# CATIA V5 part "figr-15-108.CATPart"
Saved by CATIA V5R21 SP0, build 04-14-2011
Part number: Part1
Bounding box of the stored display mesh (mm): x -60.955 to 60.955, y -33.748 to 33.748, z 0 to 6.052
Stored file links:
  D:\CATIA V5R21 E-RESOURCES\CATIA-V5R21\catia-v5r21-prt\c15-catia-v5r20-prt\c15-catia-v5r21-figr-15-108.CATPart
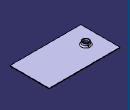
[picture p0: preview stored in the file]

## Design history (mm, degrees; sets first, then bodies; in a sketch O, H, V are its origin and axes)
SheetMetalParameters1: Thickness 1, BendRadius 5, KFactor 0.5 {= log(min(100,max(20*SheetMetalParameters1.BendRadius,SheetMetalParameters1.Thickness)/SheetMetalParameters1.Thickness))/log(100)/2}, ReliefRadialLength 1, ReliefAxialLength 2, MinimumBendRadius 0
Body1 (main body)
  Sketch1 on xy-plane, origin (0, 0, 0), H (1, 0, 0), V (0, 1, 0)
    line L1 (60.9549, 33.7477) -> (60.9549, -33.7477)
    line L2 (60.9549, -33.7477) -> (-60.9549, -33.7477)
    line L3 (-60.9549, -33.7477) -> (-60.9549, 33.7477)
    line L4 (-60.9549, 33.7477) -> (60.9549, 33.7477)
    vertical: L1 V, L3 V
    horizontal: L2 H, L4 H
    equidistance: L1 L3 O, L2 L4 O
  Wall1: Thickness 1, Profile Sketch1
  Sketch2 on face of Wall1, origin (0, 0, 1), H (1, 0, 0), V (0, 1, 0)
    point P1 (-35.8601, 0)
    coincidence: P1 H
  Sketch3 on face of Wall1, origin (-35.8601, 0, 1), H (1, 0, 0), V (0, 1, 0)
    point P1 (0, 0)
    reference projected point E1 (0, 0) from Sketch2.P1
    coincidence: E1 P1
  d_Stamp1: KFacteur 0.5 {= SheetMetalParameters1.KFactor}, Stamp_FilletRadius 2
